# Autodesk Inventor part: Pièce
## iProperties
Shininess: 64.0
Length Units: 11269
Angle Units: 11279
Time Units: 11290
Mass Units: 11283
Length Display Precision: 3
Angle Display Precision: 2
Compacted: True
Part Number: Pièce
Document SubType Name: Modeling
Created: 2004-02
Material: Par défaut
Project: GB000
Manufacturer: Standard
Standards Organization: Custom
Designer: Gilles Glemarec
Density: 0.0
Volumn: 0.0
Area: 0.0
PropertySet Name: Model Information
Control State: 0
Master: False
Checked Out: False
observation: -
Revision Number: 00
Author: Gilles Glemarec
